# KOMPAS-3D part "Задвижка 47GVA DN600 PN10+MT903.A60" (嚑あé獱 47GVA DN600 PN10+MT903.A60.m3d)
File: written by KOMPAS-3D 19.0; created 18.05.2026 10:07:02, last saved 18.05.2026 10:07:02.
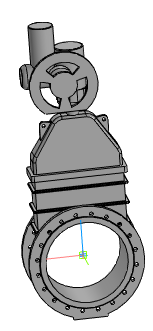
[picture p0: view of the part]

Document properties: Автор: Энергия; Полное имя файла: ..\Задвижка 47GVA DN50_DN1000+MT903.A\Задвижка 47GVA DN600 PN10+MT903.A60.a3d

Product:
- Part/product: Задвижка 47GVA DN600 PN10+MT903.A60
    Масса: 1302.15
  - Body: Электропривод МТ903.А60 без блока управления
      Масса: 346.451
  - Body: Задвижка 47GVA DN600 PN10 без исполнительного механизма
      Масса: 955.696

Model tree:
1. Операция без истории:1
2. Операция без истории:2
